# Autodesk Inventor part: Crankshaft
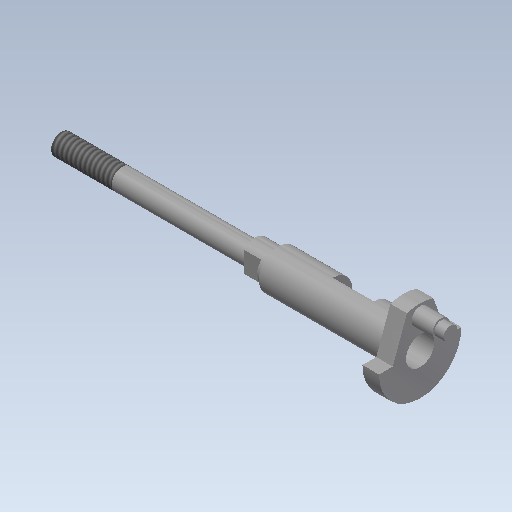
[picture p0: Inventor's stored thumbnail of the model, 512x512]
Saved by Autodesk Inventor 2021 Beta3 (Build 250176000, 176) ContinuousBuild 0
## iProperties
Created: 2012-08
Part Number: Crankshaft
Material: Steel
Document SubType Name: Modeling
Designer: John
Mass: 19.2188 g
Surface Area: 23.3403 cm^2
Volume: 2.44826 cm^3
Density: 7.85 g/cm^3
Appearance: Steel
Author: John
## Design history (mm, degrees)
sketch "Sketch1"
  geometry: C1 r 9.474 at (0, 0); 1 further point
  constraints: 1 centre point, 1 coincident
  dimensions: "d0" = 9.4742 radius of C1
extrude "Extrusion1" new body sketch "Sketch1" distance "d1" = 3.81; taper "d2" = 0 deg
sketch "Sketch2"
  geometry: C1 r 9.474 at (0, 0) reference; C2 r 4.508 at (0, 0)
  constraints: 1 centre point, 1 coincident
  dimensions: "d4" = 9.017 diameter of C2
extrude "Extrusion2" join sketch "Sketch2" distance "d6" = 32.639; taper "d7" = 0 deg
sketch "Sketch3"
  geometry: C1 r 9.474 at (0, 0) reference; C2 r 3.493 at (0, 0)
  constraints: 1 centre point, 1 coincident
  dimensions: "d9" = 6.985 diameter of C2
extrude "Extrusion3" join sketch "Sketch3" distance "d11" = 38.1; taper "d12" = 0 deg
sketch "Sketch4"
  geometry: C1 r 9.474 at (0, 0) reference; C2 r 2.413 at (0, 0)
  constraints: 1 centre point, 1 coincident
  dimensions: "d13" = 4.826 diameter of C2
extrude "Extrusion4" join sketch "Sketch4" distance "d15" = 82.55; taper "d16" = 0 deg
sketch "Sketch5"
  geometry: L1 (-3.81, 9.474)-(0, 9.474) reference; L2 (0, 9.474)-(0, -9.474) reference; L3 (0, -9.474)-(-3.81, -9.474) reference; L4 (-3.81, -9.474)-(-3.81, -4.508) reference; L5 (-3.81, -4.508)-(-32.639, -4.508) reference; L6 (-32.639, -4.508)-(-32.639, -3.493) reference; L7 (-32.639, -3.493)-(-38.1, -3.493) reference; L8 (-38.1, -3.493)-(-38.1, -2.413) reference; L9 (-38.1, -2.413)-(-82.55, -2.413) reference; L10 (-82.55, -2.413)-(-82.55, 2.413) reference; L11 (-82.55, 2.413)-(-38.1, 2.413) reference; L12 (-38.1, 2.413)-(-38.1, 3.493) reference; L13 (-38.1, 3.493)-(-32.639, 3.493) reference; L14 (-32.639, 3.493)-(-32.639, 4.508) reference; L15 (-32.639, 4.508)-(-3.81, 4.508) reference; L16 (-3.81, 4.508)-(-3.81, 9.474) reference; L17 (-38.1, 3.493)-(-34.036, 3.493); L18 (-34.036, 3.493)-(-34.036, 2.54); L19 (-34.036, 2.54)-(-38.1, 2.54); L20 (-38.1, 2.54)-(-38.1, 3.493); L21 (-38.1, -3.493)-(-34.036, -3.493); L22 (-34.036, -3.493)-(-34.036, -2.54); L23 (-34.036, -2.54)-(-38.1, -2.54); L24 (-38.1, -2.54)-(-38.1, -3.493); 1 further point
  constraints: 16 end point, 4 parallel, 2 collinear, 2 horizontal, 2 perpendicular
  dimensions: "d17" = 34.036 distance between parallel lines of L2 L18; "d18" = 5.08 distance between parallel lines of L23 L19
extrude "Extrusion5" cut sketch "Sketch5" extent not by distance; stored distance "d19" = 54.61; taper "d20" = 0 deg
thread "Thread1" dims "d21" = 13.97, "d22" = 0
sketch "Sketch6"
  geometry: C1 r 9.474 at (0, 0) reference
hole "Hole1" sketch "Sketch6" at (0, 0) diameter "d23" = 6.5278; stored, may be unused: countersink angle "d27" = 82 deg, drill point angle "d29" = 0 deg; dims "d24" = 19.05, "d25" = 3.0226, "d26" = 6.35, "d28" = 22.352
sketch "Sketch7"
  geometry: L1 (-3.81, 9.474)-(0, 9.474) reference; L2 (0, 9.474)-(0, 3.264) reference; L3 (0, 3.264)-(-22.352, 3.264) reference; L4 (-22.352, 3.264)-(-22.352, -3.264) reference; L5 (-22.352, -3.264)-(0, -3.264) reference; L6 (0, -3.264)-(0, -9.474) reference; L7 (0, -9.474)-(-3.81, -9.474) reference; L8 (-3.81, -9.474)-(-3.81, -4.508) reference; L9 (-3.81, -4.508)-(-32.639, -4.508) reference; L10 (-32.639, -4.508)-(-32.639, -3.493) reference; L11 (-32.639, -3.493)-(-34.036, -3.493) reference; L12 (-34.036, -3.493)-(-34.036, -2.54) reference; L13 (-34.036, -2.54)-(-38.1, -2.54) reference; L14 (-38.1, -2.54)-(-38.1, -2.413) reference; L15 (-38.1, -2.413)-(-82.55, -2.413) reference; L16 (-82.55, -2.413)-(-82.55, 2.413) reference; L17 (-82.55, 2.413)-(-38.1, 2.413) reference; L18 (-38.1, 2.413)-(-38.1, 2.54) reference; L19 (-38.1, 2.54)-(-34.036, 2.54) reference; L20 (-34.036, 2.54)-(-34.036, 3.493) reference; L21 (-34.036, 3.493)-(-32.639, 3.493) reference; L22 (-32.639, 3.493)-(-32.639, 4.508) reference; L23 (-32.639, 4.508)-(-3.81, 4.508) reference; L24 (-3.81, 4.508)-(-3.81, 9.474) reference; L25 (-65.532, 0)-(10.922, 0) reference; L26 (-10.668, 0)-(-20.117, 0); L27 (-20.117, 0)-(-20.117, 4.508); L28 (-20.117, 4.508)-(-10.668, 4.508); L29 (-10.668, 4.508)-(-10.668, 0); 1 further point
  constraints: 8 end point, 2 parallel, 2 point on line, 1 horizontal, 1 perpendicular
  dimensions: "d30" = 10.668 distance between parallel lines of L2 L29; "d31" = 20.1168 distance between parallel lines of L2 L27
extrude "Extrusion6" cut sketch "Sketch7" extent not by distance; stored distance "d32" = 54.61; taper "d33" = 0 deg
sketch "Sketch8"
  geometry: L1 (0, -9.474)-(0, -6.299); L2 (0, -6.299)-(-8.976, -3.032); L3 (0, 0)-(-9.474, 0); L4 (0, 9.474)-(0, 6.299); L5 (0, 6.299)-(-8.976, 3.032); C1 r 3.264 at (0, 0) reference; A1 r 9.474 centre (0, 0) between (0, -9.474) and (-8.976, -3.032) reference
  constraints: 10 end point, 5 point on circle, 2 perpendicular, 1 collinear, 1 vertical, 1 vertical alignment, 1 other
  dimensions: "d34" = 3.175 distance of L1.start L1.end; "d36" = 110 deg angle of L2 L1
extrude "Extrusion7" cut sketch "Sketch8" extent not by distance; stored distance "d40" = 54.61; taper "d41" = 0 deg
sketch "Sketch9"
  geometry: C1 r 1.994 at (-6.934, 0); A1 r 9.474 centre (0, 0) between (0, -9.474) and (0, 9.474) reference
  constraints: 1 centre point
  dimensions: "d43" = 6.9342 distance of A1.centre C1.centre; "d47" = 3.9878 diameter of C1
extrude "Extrusion8" join sketch "Sketch9" distance "d44" = 4.826; taper "d45" = 0 deg
sketch "Sketch10"
  geometry: C1 r 1.994 at (0, 0) reference; C2 r 1.587 at (0, 0); 1 further point
  constraints: 1 centre point, 1 coincident
  dimensions: "d49" = 3.175 diameter of C2
extrude "Extrusion9" join sketch "Sketch10" distance "d51" = 2.159; taper "d52" = 0 deg
body "Solid1"
node "Project Cut Edges1"
node "Project Cut Edges2"
